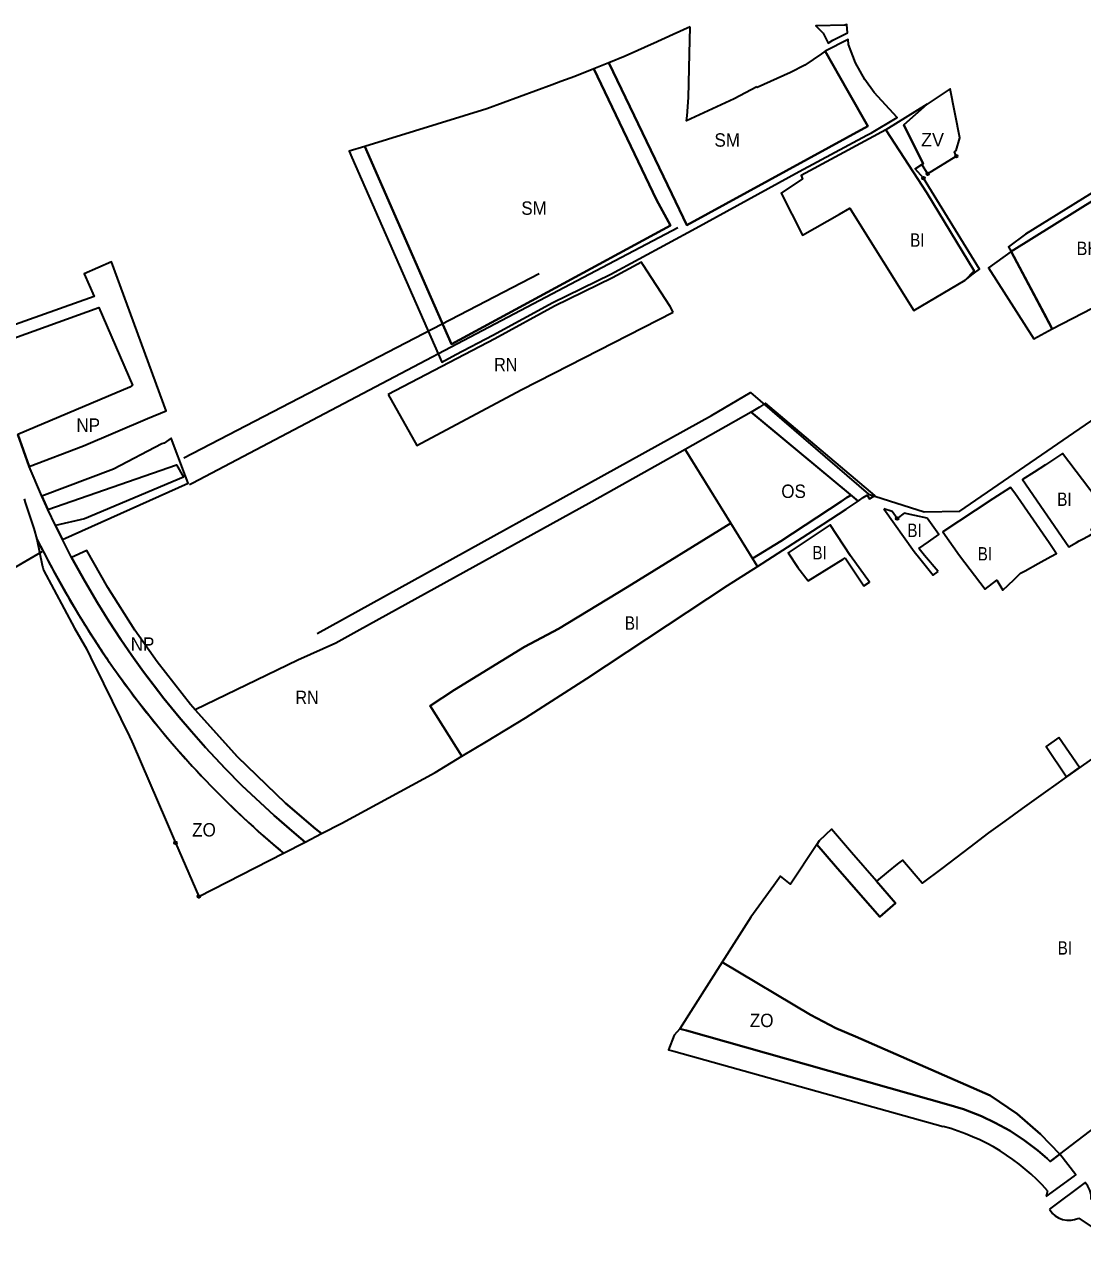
# Model space of a CAD drawing. Extents: x -650276 to -642489, y -1074311 to -1066658.
# Drawn here: x -649019 to -648072, y -1071488 to -1070387 of the extents above; entities that cross this region are included whole.
import ezdxf

# ---------------------------------------------------------------- set-up
doc = ezdxf.new("R2010")
doc.units = 0
doc.header["$LTSCALE"] = 4.8
doc.header["$PDMODE"] = 32
doc.header["$PDSIZE"] = 2.4
for name, color, linetype, lineweight in [('1', 7, 'Continuous', 35), ('15', 7, 'Continuous', 35), ('18', 7, 'Continuous', 35), ('2', 7, 'Continuous', 35), ('24', 7, 'Continuous', 35), ('40', 7, 'Continuous', 35), ('42', 7, 'Continuous', 35), ('48', 7, 'Continuous', 35), ('54', 7, 'Continuous', 35), ('7', 7, 'Continuous', 35), ('9', 7, 'Continuous', 35)]:
    doc.layers.add(name, color=color, linetype=linetype, lineweight=lineweight)
doc.layers.add('62', color=7, linetype='Continuous')
doc.layers.add('63', color=7, linetype='Continuous')

msp = doc.modelspace()

# ---------------------------------------------------------------- linework, layer by layer
at = {"layer": '1'}
msp.add_lwpolyline([(-648098.637, -1070659.682), (-648007.838, -1070612.851), (-648019, -1070518), (-648135.47, -1070590.61), (-648105.98, -1070645.91)], close=True, dxfattribs=at)
at = {"layer": '15'}
for p, q in [((-648272.453, -1070814.072), (-648271.1, -1070813.17)), ((-648303.631, -1070834.849), (-648283.19, -1070821.23))]:
    msp.add_line(p, q, dxfattribs=at)
for points in [[(-648303.705, -1070395.035), (-648302.028, -1070398.436), (-648299.32, -1070403.93), (-648295.18, -1070401.23), (-648281.907, -1070394.762), (-648282.582, -1070387.276), (-648284.37, -1070387.85), (-648310.275, -1070388.476)], [(-648550.72, -1070626.869), (-648636.757, -1070673.431), (-648655.178, -1070631.294), (-648714.161, -1070496.376), (-648728.255, -1070500.709), (-648725.835, -1070506.221), (-648668.207, -1070637.453), (-648645.331, -1070689.546), (-648632.652, -1070682.82), (-648599.66, -1070665.32), (-648545.76, -1070636.22), (-648494.04, -1070610.73), (-648417.855, -1070569.57), (-648325.21, -1070518.84), (-648264.56, -1070486.34), (-648260.57, -1070484.2), (-648237.475, -1070470.361), (-648257.96, -1070448.17), (-648266.416, -1070436.404), (-648274.808, -1070421.647), (-648280.974, -1070405.11), (-648281.388, -1070400.523), (-648302.01, -1070411.05), (-648282.01, -1070446.35), (-648263.859, -1070478.393), (-648425.835, -1070567.021), (-648439.409, -1070538.729), (-648495.666, -1070421.476), (-648509.227, -1070426.957), (-648452.97, -1070544.21), (-648440.531, -1070567.236)], [(-648007.838, -1070612.851), (-647999.588, -1070608.596), (-648002, -1070588), (-648010.831, -1070512.588), (-647999.756, -1070505.655), (-647981.81, -1070496.06), (-647950.48, -1070482.79), (-647917.98, -1070472.47), (-647918.54, -1070468.61), (-647918.95, -1070462.36), (-647923.53, -1070462.75), (-647923.247, -1070465.749), (-647953.251, -1070475.276), (-647985.19, -1070488.804), (-647991.539, -1070492.016), (-648005.668, -1070434.145), (-648014.63, -1070439.36), (-648000.442, -1070499.336), (-648019.789, -1070511.293), (-648050.38, -1070530.2), (-648122.57, -1070575), (-648137.78, -1070586.25), (-648135.47, -1070590.61), (-648019, -1070518)], [(-648135.47, -1070590.61), (-648155.582, -1070605.295), (-648115.057, -1070668.651), (-648098.637, -1070659.682)], [(-648092.72, -1071025.89), (-648104.12, -1071033.78), (-648085.73, -1071060.92), (-648074.12, -1071052.75)], [(-648238.84, -1071174.33), (-648256.04, -1071154.5), (-648278.39, -1071128.74), (-648296.34, -1071108.04), (-648307.33, -1071118.47), (-648309.41, -1071121.655), (-648292.587, -1071141.054), (-648270.236, -1071166.815), (-648253.126, -1071186.542)]]:
    msp.add_lwpolyline(points, close=True, dxfattribs=at)
for points in [[(-648213.87, -1070524.8), (-648221.359, -1070516.349), (-648215.48, -1070512.59), (-648214.34, -1070511.86), (-648231.53, -1070476.99), (-648210.48, -1070458.42), (-648247.67, -1070481.57), (-648211, -1070538), (-648168.575, -1070607.847), (-648176.54, -1070616.09)], [(-648176.54, -1070616.09), (-648169.28, -1070610.49), (-648163.8, -1070606.27), (-648213.87, -1070524.8), (-648221.359, -1070516.349), (-648215.48, -1070512.59), (-648214.34, -1070511.86), (-648231.53, -1070476.99), (-648210.48, -1070458.42), (-648247.67, -1070481.57), (-648211, -1070538)], [(-648176.54, -1070616.09), (-648169.28, -1070610.49), (-648163.8, -1070606.27), (-648213.87, -1070524.8)], [(-648211, -1070538), (-648168.575, -1070607.847), (-648176.54, -1070616.09)], [(-648271.1, -1070813.17), (-648267.8, -1070810.96), (-648264.38, -1070808.66), (-648262.15, -1070811.96), (-648257.61, -1070808.91), (-648355.275, -1070726.455), (-648360.83, -1070729.87), (-648366.739, -1070733.501), (-648368.163, -1070734.376), (-648272.453, -1070814.072)], [(-648283.19, -1070821.23), (-648272.45, -1070814.075), (-648278.832, -1070808.761), (-648282.44, -1070810.84), (-648287.74, -1070814.32)], [(-648287.74, -1070814.32), (-648341.58, -1070849.98), (-648366.98, -1070865.44)], [(-648366.98, -1070865.44), (-648362.519, -1070872.788), (-648303.631, -1070834.849)]]:
    msp.add_lwpolyline(points, dxfattribs=at)
msp.add_point((-648213.87, -1070524.8), dxfattribs=at)
at = {"layer": '18'}
for points in [[(-648423.005, -1070389.357), (-648438.21, -1070396.22), (-648455.85, -1070404.19), (-648457.94, -1070405.13), (-648469.77, -1070410.47)], [(-648363.1, -1070443.1), (-648383.61, -1070453.86), (-648426.05, -1070473.34), (-648425.71, -1070468.87), (-648424.47, -1070452.7), (-648423.56, -1070413.35), (-648423.005, -1070389.357)], [(-648469.77, -1070410.47), (-648481.18, -1070415.62), (-648495.666, -1070421.476), (-648439.409, -1070538.729)], [(-648439.409, -1070538.729), (-648425.835, -1070567.021), (-648263.859, -1070478.393), (-648282.01, -1070446.35), (-648302.01, -1070411.05)], [(-648302.01, -1070411.05), (-648305.39, -1070413.38), (-648320.24, -1070423.64), (-648332.97, -1070430.18), (-648362.79, -1070443.63), (-648363.1, -1070443.1)]]:
    msp.add_lwpolyline(points, dxfattribs=at)
msp.add_lwpolyline([(-648636.757, -1070673.431), (-648550.72, -1070626.869), (-648440.531, -1070567.236), (-648452.97, -1070544.21), (-648509.227, -1070426.957), (-648526.28, -1070433.85), (-648538.611, -1070438.388), (-648546.377, -1070441.246), (-648604.92, -1070462.79), (-648714.161, -1070496.376), (-648655.178, -1070631.294)], close=True, dxfattribs=at)
at = {"layer": '2'}
for points in [[(-648247.67, -1070481.57), (-648262.69, -1070489.67), (-648323.59, -1070522.48), (-648322.18, -1070525.44), (-648341.41, -1070538.42), (-648322.16, -1070575.76), (-648289.22, -1070557.15), (-648279.736, -1070551.783), (-648278.89, -1070553.14), (-648222.58, -1070643.48), (-648176.54, -1070616.09), (-648168.575, -1070607.847), (-648211, -1070538)], [(-648114.77, -1070788.08), (-648125.2, -1070794.79), (-648083.65, -1070854.89), (-648076.73, -1070851.07), (-648074.41, -1070849.79), (-648072.59, -1070848.79), (-648065.35, -1070844.8), (-648061.52, -1070842.68), (-648063.76, -1070839.49), (-648056.61, -1070834.26), (-648047.17, -1070827.35), (-648089.27, -1070771.57), (-648104.78, -1070781.65)], [(-648167.6, -1070822.53), (-648196.65, -1070841.7), (-648181.75, -1070862.74), (-648158.58, -1070892.98), (-648148.34, -1070884.92), (-648142.79, -1070893.78), (-648133.14, -1070884.6), (-648127, -1070878.75), (-648122.72, -1070876.44), (-648111.24, -1070870.11), (-648099.85, -1070863.82), (-648094.9, -1070861.09), (-648095.42, -1070860.3), (-648101.45, -1070851.34), (-648132.03, -1070807.05), (-648136.08, -1070801.79), (-648151.77, -1070812.11)], [(-648540.7, -1070928.6), (-648571.14, -1070944.67), (-648634.07, -1070983.17), (-648655.76, -1070997.5), (-648627.39, -1071042.65), (-648605.3, -1071029.34), (-648570.23, -1071008.2), (-648515.46, -1070972.94), (-648389.33, -1070889.79), (-648362.519, -1070872.788), (-648386.587, -1070833.807), (-648479.18, -1070891.26)]]:
    msp.add_lwpolyline(points, close=True, dxfattribs=at)
for points in [[(-648237.46, -1070829.68), (-648241.96, -1070823.46), (-648249.5, -1070821.08)], [(-648249.5, -1070821.08), (-648222.158, -1070859.221), (-648217.1, -1070865.56), (-648205.18, -1070880.5), (-648200.86, -1070877.05)], [(-648210.517, -1070829.445), (-648221.58, -1070827.03), (-648231.22, -1070824.92), (-648237.46, -1070829.68)], [(-648218.11, -1070856.44), (-648209.37, -1070850.44), (-648200.17, -1070844.094), (-648210.517, -1070829.445)], [(-648284.02, -1070864.91), (-648267.24, -1070889.9), (-648262.4, -1070886.58), (-648279.39, -1070862.98), (-648297.39, -1070835.36), (-648320.02, -1070850.16), (-648335.19, -1070860.49), (-648326.41, -1070873.55), (-648317.14, -1070885.48)], [(-648200.86, -1070877.05), (-648212.94, -1070862.74), (-648217.85, -1070856.93), (-648218.11, -1070856.44)], [(-648317.14, -1070885.48), (-648285.72, -1070865.96), (-648284.02, -1070864.91)], [(-648062.53, -1071044.59), (-648085.73, -1071060.92), (-648097.61, -1071069.37), (-648102.55, -1071072.86), (-648125.53, -1071089.51), (-648141.12, -1071100.71), (-648155.77, -1071111.23), (-648172.48, -1071123.95), (-648197.57, -1071143.03), (-648215.08, -1071156.35), (-648232.8, -1071135.6), (-648237.46, -1071139.38), (-648245.49, -1071145.91), (-648256.04, -1071154.5), (-648238.84, -1071174.33), (-648253.126, -1071186.542), (-648292.587, -1071141.054), (-648309.41, -1071121.655), (-648333.002, -1071157.07), (-648341.943, -1071150.071), (-648347.949, -1071158.385), (-648368.48, -1071186.81), (-648394.104, -1071227.17), (-648315.127, -1071274.052), (-648292.406, -1071286.112), (-648274.918, -1071293.751), (-648154.21, -1071346.477), (-648130, -1071363), (-648109, -1071381), (-648091.92, -1071399.07), (-648060.01, -1071374.69)]]:
    msp.add_lwpolyline(points, dxfattribs=at)
msp.add_point((-648237.46, -1070829.68), dxfattribs=at)
at = {"layer": '24'}
for points in [[(-649019.48, -1070812.18), (-649018.48, -1070815.18), (-649011.24, -1070836.79), (-649010.67, -1070838.5), (-649007.885, -1070848.153), (-648994.464, -1070873.974), (-648982.467, -1070895.704), (-648970.712, -1070915.663), (-648960.268, -1070932.429), (-648949.389, -1070949.031), (-648939.232, -1070963.818), (-648918.601, -1070991.969), (-648896.068, -1071020.184), (-648886.874, -1071031.044), (-648874.793, -1071044.773), (-648863.847, -1071056.723), (-648851.175, -1071069.886), (-648838.696, -1071082.562), (-648823.087, -1071097.562), (-648816.379, -1071103.782), (-648806.239, -1071112.938), (-648797, -1071121), (-648790.23, -1071126.818), (-648787.207, -1071129.363), (-648767.824, -1071119.455), (-648771.725, -1071116.233), (-648781.806, -1071107.721), (-648795.407, -1071095.8), (-648824.292, -1071068.677), (-648839.273, -1071053.556), (-648856.883, -1071034.761), (-648869.629, -1071020.411), (-648880.44, -1071007.703), (-648894.164, -1070990.806), (-648902.714, -1070979.812), (-648912.396, -1070966.893), (-648922.92, -1070952.242), (-648932.78, -1070937.887), (-648943.414, -1070921.659), (-648953.605, -1070905.299), (-648965.093, -1070885.794), (-648976.834, -1070864.527), (-648985.145, -1070848.538), (-648991.386, -1070835.954), (-648998.132, -1070821.723), (-649003.641, -1070809.566), (-649014.888, -1070782.994), (-649025.129, -1070754.377)], [(-648103.894, -1071436.836), (-648079.108, -1071418.564), (-648077.53, -1071417.4), (-648091.92, -1071399.07), (-648100.438, -1071405.517), (-648103.268, -1071402.88), (-648111.646, -1071395.618), (-648123.313, -1071386.696), (-648136.263, -1071378.194), (-648149.571, -1071370.788), (-648162.084, -1071364.918), (-648178.158, -1071358.781), (-648191.25, -1071354.858), (-648426.18, -1071288.32), (-648432.093, -1071286.645), (-648437.16, -1071292.53), (-648442.191, -1071305.453), (-648437.454, -1071306.778), (-648196.236, -1071374.226)], [(-648063.593, -1071439.723), (-648063.862, -1071435.078), (-648064.838, -1071431.28), (-648066.623, -1071427.592), (-648069.022, -1071424.443), (-648101.203, -1071448.31)], [(-648101.203, -1071448.31), (-648098.259, -1071452.196), (-648096.014, -1071454.192), (-648093.059, -1071456.066), (-648089.539, -1071457.489), (-648085.585, -1071458.248), (-648081.642, -1071458.215), (-648078.539, -1071457.636), (-648074.86, -1071456.248)], [(-648074.86, -1071456.248), (-648027.562, -1071487.894)]]:
    msp.add_lwpolyline(points, dxfattribs=at)
for centre, radius, start, end in [((-648244.965, -1071557.871), 190, 41.59858, 75.13936), ((-648083.781, -1071438.172), 20.157, 161.35794, 176.20098)]:
    msp.add_arc(centre, radius, start, end, dxfattribs=at)
at = {"layer": '40'}
msp.add_line((-648210.19, -1070521.07), (-648184.54, -1070505.07), dxfattribs=at)
for points in [[(-648184.54, -1070505.07), (-648186.088, -1070501.313), (-648184.791, -1070500.073), (-648181.386, -1070488.724), (-648189.93, -1070444.71), (-648194.56, -1070447.8), (-648194.56, -1070447.799), (-648209.82, -1070457.98), (-648210.48, -1070458.42), (-648231.53, -1070476.99), (-648214.34, -1070511.86)], [(-648214.34, -1070511.86), (-648215.48, -1070512.59), (-648210.19, -1070521.07)]]:
    msp.add_lwpolyline(points, dxfattribs=at)
for p in [(-648184.54, -1070505.07), (-648210.19, -1070521.07)]:
    msp.add_point(p, dxfattribs=at)
at = {"layer": '42'}
for p, q in [((-648883.73, -1071120.13), (-648862.97, -1071168.09)), ((-648862.97, -1071168.09), (-648787.207, -1071129.363)), ((-648394.104, -1071227.17), (-648432.093, -1071286.645))]:
    msp.add_line(p, q, dxfattribs=at)
for points in [[(-649002.97, -1070857.609), (-649007.885, -1070848.153), (-649003.1, -1070871.35), (-649002.82, -1070872.69), (-649002.62, -1070873.69), (-649002.15, -1070875.96), (-648974.4, -1070927.77), (-648963.5, -1070946.45), (-648959.92, -1070953.73), (-648948.29, -1070977.37), (-648924.92, -1071024.89), (-648922.98, -1071029.49), (-648921.87, -1071032.04), (-648892.82, -1071099.15), (-648883.73, -1071120.13)], [(-648994.42, -1070874.053), (-648994.464, -1070873.974), (-648994.52, -1070873.867)], [(-648982.403, -1070895.812), (-648982.467, -1070895.704), (-648982.524, -1070895.601)], [(-648970.64, -1070915.778), (-648970.712, -1070915.663), (-648970.771, -1070915.564)], [(-648960.194, -1070932.542), (-648960.268, -1070932.429), (-648960.34, -1070932.313)], [(-648949.345, -1070949.096), (-648949.389, -1070949.031), (-648949.428, -1070948.972)], [(-648939.179, -1070963.89), (-648939.232, -1070963.818), (-648939.33, -1070963.675)], [(-648918.464, -1070992.141), (-648918.601, -1070991.969), (-648918.737, -1070991.784)], [(-648292.406, -1071286.112), (-648315.127, -1071274.052), (-648394.104, -1071227.17), (-648432.093, -1071286.645)], [(-648091.92, -1071399.07), (-648109, -1071381), (-648130, -1071363), (-648154.21, -1071346.477), (-648274.918, -1071293.751), (-648292.406, -1071286.112)], [(-648432.093, -1071286.645), (-648426.18, -1071288.32), (-648191.25, -1071354.858)], [(-648191.25, -1071354.858), (-648178.158, -1071358.781), (-648162.084, -1071364.918), (-648149.571, -1071370.788), (-648136.263, -1071378.194), (-648123.313, -1071386.696), (-648111.646, -1071395.618), (-648103.268, -1071402.88), (-648100.438, -1071405.517), (-648091.92, -1071399.07)]]:
    msp.add_lwpolyline(points, dxfattribs=at)
for start, end in [(206.85611, 208.07207), (208.08607, 209.71957), (209.73567, 211.25686), (211.27351, 212.56631), (212.58435, 213.8879), (213.89777, 215.07157), (215.08899, 217.38409), (217.41391, 230.04071)]:
    msp.add_arc((-648232.695, -1070467.567), 863.398, start, end, dxfattribs=at)
for p in [(-648883.73, -1071120.13), (-648862.97, -1071168.09)]:
    msp.add_point(p, dxfattribs=at)
at = {"layer": '48'}
msp.add_line((-648894.164, -1070990.806), (-648880.44, -1071007.703), dxfattribs=at)
for points in [[(-649014.888, -1070782.994), (-648966.35, -1070764.7), (-648908.94, -1070740.19), (-648892.215, -1070733.293), (-648927.2, -1070637.98), (-648941.064, -1070599.735), (-648965.569, -1070610.382), (-648956.687, -1070630.825), (-649050.081, -1070663.981), (-649047.11, -1070674.743), (-648952.455, -1070640.564), (-648922.196, -1070710.207), (-648924.668, -1070712.022), (-648943.837, -1070720.104), (-649025.129, -1070754.377)], [(-648985.145, -1070848.538), (-648872.375, -1070798.112), (-648874.87, -1070791.61), (-648887.84, -1070757.84), (-648894.08, -1070762.22), (-648896.11, -1070762.73), (-648939.5, -1070785.4), (-649003.641, -1070809.566), (-648998.132, -1070821.723), (-648882.919, -1070781.673), (-648876.64, -1070792.6), (-648965.475, -1070829.829), (-648991.386, -1070835.954)]]:
    msp.add_lwpolyline(points, close=True, dxfattribs=at)
for points in [[(-648866.341, -1071000.881), (-648870.479, -1070996.265), (-648900.337, -1070957.964), (-648920.293, -1070929.567), (-648944.376, -1070891.404), (-648963.107, -1070858.328), (-648976.834, -1070864.527)], [(-648976.834, -1070864.527), (-648965.093, -1070885.794), (-648953.605, -1070905.299), (-648943.414, -1070921.659), (-648932.78, -1070937.887), (-648922.92, -1070952.242), (-648912.396, -1070966.893), (-648894.164, -1070990.806)], [(-648880.44, -1071007.703), (-648869.629, -1071020.411), (-648856.883, -1071034.761), (-648839.273, -1071053.556), (-648824.292, -1071068.677), (-648795.407, -1071095.8), (-648777.641, -1071111.238), (-648771.725, -1071116.233), (-648767.824, -1071119.455), (-648752.967, -1071111.861), (-648758.423, -1071107.756), (-648785.386, -1071084.634), (-648828.353, -1071043.265), (-648866.341, -1071000.881)]]:
    msp.add_lwpolyline(points, dxfattribs=at)
at = {"layer": '54'}
for p, q in [((-648876.429, -1070775.252), (-648558.121, -1070610.206)), ((-649003.638, -1070859.543), (-649266.084, -1071012.071))]:
    msp.add_line(p, q, dxfattribs=at)
for points in [[(-648433.898, -1070569.36), (-648868.299, -1070798.03), (-648871.326, -1070799.464)], [(-648756.915, -1070932.76), (-648403.845, -1070737.419), (-648368.964, -1070716.905), (-648263.103, -1070807.79), (-648213.358, -1070823.563), (-648181.392, -1070823.076), (-647966.625, -1070675.686), (-647777.125, -1070608.309)]]:
    msp.add_lwpolyline(points, dxfattribs=at)
at = {"layer": '7'}
for points in [[(-648438.13, -1070644.73), (-648440.8, -1070639.72), (-648465.28, -1070602.24), (-648466.61, -1070600.21), (-648492.47, -1070614.2), (-648544.42, -1070639.42), (-648597.74, -1070668.62), (-648693.45, -1070718.46)], [(-648693.45, -1070718.46), (-648667.72, -1070764.15), (-648574.27, -1070714.5), (-648544.906, -1070699.451), (-648438.13, -1070644.73)]]:
    msp.add_lwpolyline(points, dxfattribs=at)
msp.add_lwpolyline([(-648866.341, -1071000.881), (-648828.353, -1071043.265), (-648785.386, -1071084.634), (-648758.423, -1071107.756), (-648752.967, -1071111.861), (-648734.849, -1071102.599), (-648651.375, -1071057.109), (-648627.39, -1071042.65), (-648655.76, -1070997.5), (-648634.07, -1070983.17), (-648571.14, -1070944.67), (-648540.7, -1070928.6), (-648479.18, -1070891.26), (-648386.587, -1070833.807), (-648427.25, -1070767.95), (-648511.09, -1070814.7), (-648721.54, -1070930.88), (-648740.25, -1070941.21), (-648774.23, -1070956.42)], close=True, dxfattribs=at)
at = {"layer": '9'}
msp.add_lwpolyline([(-648368.163, -1070734.376), (-648427.25, -1070767.95), (-648366.98, -1070865.44), (-648341.58, -1070849.98), (-648287.74, -1070814.32), (-648282.44, -1070810.84), (-648278.832, -1070808.761)], close=True, dxfattribs=at)

# ---------------------------------------------------------------- texts
at = {"layer": '62'}
msp.add_text('ZV', height=12, dxfattribs=at).set_placement((-648216.069, -1070496.39))
for s, width, p in [('SM', 0.95, (-648574.138, -1070557.646)), ('BI', 0.85, (-648225.838, -1070586.256)), ('BH', 0.9, (-648076.769, -1070593.709)), ('RN', 0.9, (-648598.428, -1070697.883)), ('NP', 0.95, (-648972.583, -1070752.041)), ('OS', 0.95, (-648341.265, -1070811.272)), ('BI', 0.85, (-648094.127, -1070818.398)), ('BI', 0.85, (-648228.397, -1070846.265)), ('BI', 0.85, (-648313.397, -1070866.265)), ('BI', 0.85, (-648165.397, -1070867.265)), ('BI', 0.85, (-648481.397, -1070929.265)), ('NP', 0.95, (-648923.942, -1070948.157)), ('RN', 0.9, (-648776.428, -1070995.883)), ('ZO', 0.95, (-648868.886, -1071114.486)), ('BI', 0.85, (-648093.764, -1071220.263)), ('ZO', 0.95, (-648369.423, -1071285.188))]:
    msp.add_text(s, height=12, dxfattribs=dict(at, width=width)).set_placement(p)
at = {"layer": '63', "width": 0.95}
msp.add_text('SM', height=12, dxfattribs=at).set_placement((-648401.138, -1070496.646))

doc.saveas('drawing.dxf')
